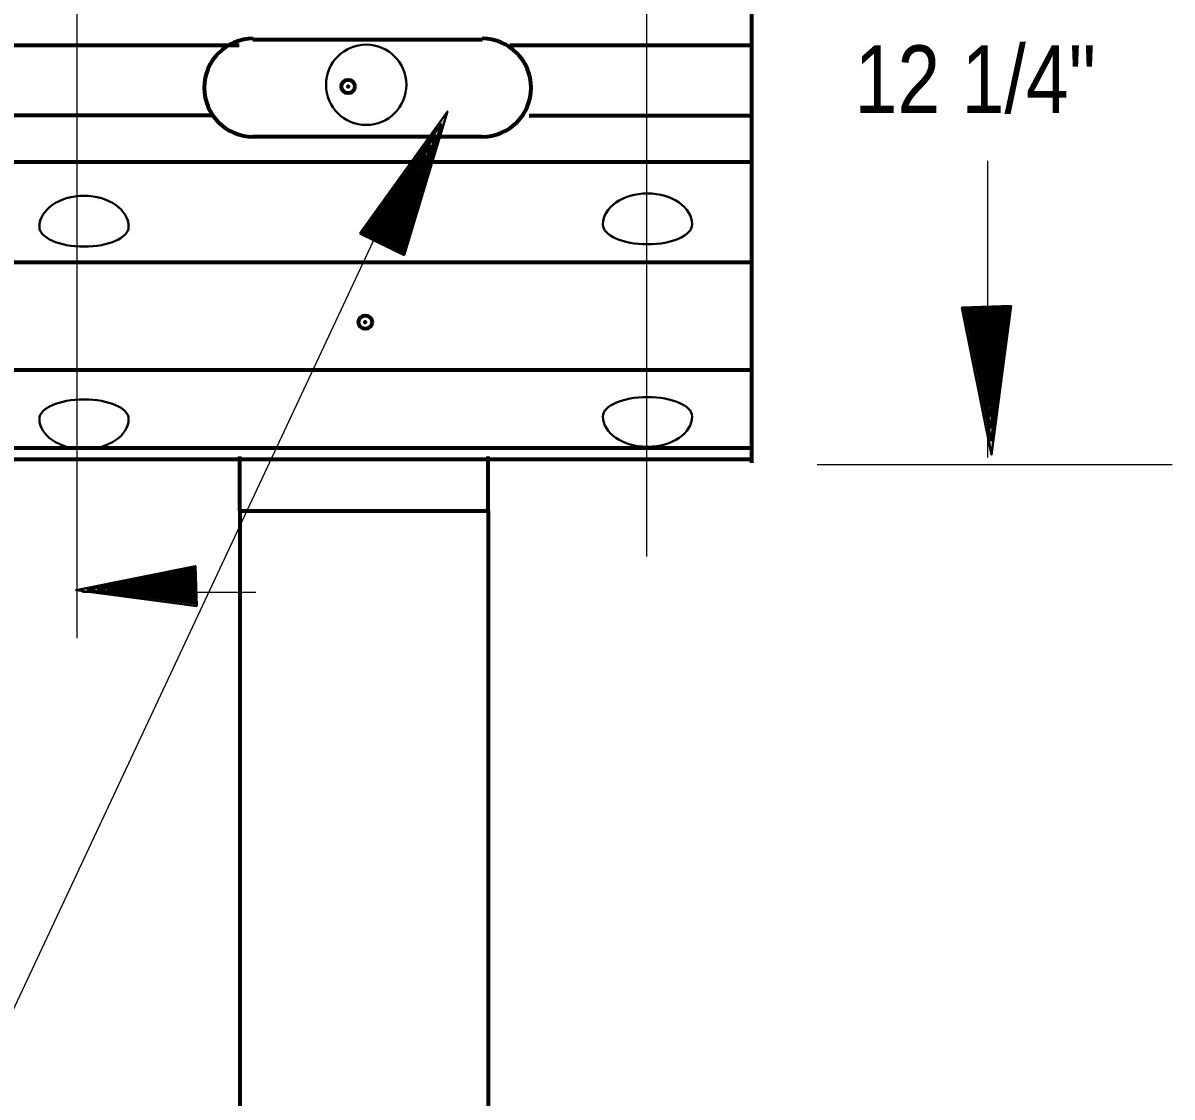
# Model space of a CAD drawing. Extents: x 895.6 to 930.4, y -2278.6 to -2254.7.
# Drawn here: x 921.428 to 923.608, y -2263.475 to -2261.437 of the extents above; entities that cross this region are included whole.
import ezdxf

# ---------------------------------------------------------------- set-up
doc = ezdxf.new("R2010")
doc.units = 0
doc.header["$LTSCALE"] = 0.051
doc.header["$PDMODE"] = 32
doc.header["$PDSIZE"] = 0.0255
for name, color, linetype, lineweight in [('1', 7, 'Continuous', 70), ('3', 7, 'Continuous', 40), ('35', 7, 'Continuous', 70)]:
    doc.layers.add(name, color=color, linetype=linetype, lineweight=lineweight)

msp = doc.modelspace()

# ---------------------------------------------------------------- hatches: boundary and pattern name
at = {"layer": '3'}
for points in [[(922.06675, -2261.83625), (922.15092, -2261.87758), (922.23292, -2261.60483), (922.23292, -2261.60483)], [(922.07158, -2261.83708), (922.14717, -2261.87433), (922.22108, -2261.62892), (922.22108, -2261.62892)], [(922.076, -2261.83792), (922.14392, -2261.87142), (922.21042, -2261.65058), (922.21042, -2261.65058)], [(922.07967, -2261.83875), (922.14075, -2261.86883), (922.20075, -2261.67008), (922.20075, -2261.67008)], [(922.08308, -2261.83942), (922.13817, -2261.86642), (922.19208, -2261.68758), (922.19208, -2261.68758)], [(922.08625, -2261.83983), (922.13592, -2261.86433), (922.18442, -2261.70333), (922.18442, -2261.70333)], [(922.08917, -2261.84067), (922.13375, -2261.86267), (922.17742, -2261.71758), (922.17742, -2261.71758)], [(922.09167, -2261.84083), (922.13167, -2261.86083), (922.171, -2261.73042), (922.171, -2261.73042)], [(922.09367, -2261.84158), (922.13017, -2261.85917), (922.16542, -2261.74192), (922.16542, -2261.74192)], [(922.096, -2261.84183), (922.12875, -2261.85783), (922.16025, -2261.75225), (922.16025, -2261.75225)], [(922.09792, -2261.84217), (922.12708, -2261.85658), (922.15575, -2261.76167), (922.15575, -2261.76167)], [(922.09958, -2261.84267), (922.12575, -2261.85542), (922.15167, -2261.77008), (922.15167, -2261.77008)], [(922.101, -2261.84275), (922.12467, -2261.85442), (922.14775, -2261.77775), (922.14775, -2261.77775)], [(922.10242, -2261.84292), (922.12367, -2261.85367), (922.1445, -2261.78417), (922.1445, -2261.78417)], [(922.10358, -2261.84317), (922.12275, -2261.85275), (922.14142, -2261.79033), (922.14142, -2261.79033)], [(922.10458, -2261.84342), (922.12208, -2261.85217), (922.139, -2261.79592), (922.139, -2261.79592)], [(922.10575, -2261.84375), (922.12142, -2261.85142), (922.1365, -2261.80083), (922.1365, -2261.80083)], [(922.10658, -2261.84392), (922.12058, -2261.85083), (922.13442, -2261.80525), (922.13442, -2261.80525)], [(922.10725, -2261.84375), (922.11992, -2261.85025), (922.13217, -2261.80917), (922.13217, -2261.80917)], [(922.10792, -2261.84392), (922.11925, -2261.84967), (922.1305, -2261.81267), (922.1305, -2261.81267)], [(922.10842, -2261.84375), (922.11875, -2261.84883), (922.12858, -2261.81575), (922.12858, -2261.81575)], [(922.10908, -2261.84417), (922.11825, -2261.84867), (922.12717, -2261.81875), (922.12717, -2261.81875)], [(922.10958, -2261.84425), (922.11792, -2261.84825), (922.12617, -2261.82142), (922.12617, -2261.82142)], [(922.11008, -2261.84425), (922.1175, -2261.84792), (922.12475, -2261.82367), (922.12475, -2261.82367)], [(923.30275, -2261.97392), (923.20917, -2261.97717), (923.26542, -2262.25633), (923.26542, -2262.25633)], [(923.29808, -2261.97542), (923.21383, -2261.97825), (923.26442, -2262.22942), (923.26442, -2262.22942)], [(923.29383, -2261.97667), (923.21817, -2261.97925), (923.26375, -2262.20533), (923.26375, -2262.20533)], [(923.29017, -2261.97783), (923.22208, -2261.98017), (923.26308, -2262.18367), (923.26308, -2262.18367)], [(923.28692, -2261.97875), (923.22558, -2261.98092), (923.26242, -2262.16417), (923.26242, -2262.16417)], [(923.28375, -2261.97992), (923.22858, -2261.98175), (923.26183, -2262.14658), (923.26183, -2262.14658)], [(923.28092, -2261.98067), (923.23125, -2261.98225), (923.26125, -2262.13075), (923.26125, -2262.13075)], [(923.27867, -2261.98158), (923.23383, -2261.98283), (923.26083, -2262.11633), (923.26083, -2262.11633)], [(923.27642, -2261.98192), (923.23608, -2261.98358), (923.26025, -2262.10367), (923.26025, -2262.10367)], [(923.27433, -2261.98275), (923.23792, -2261.98408), (923.25992, -2262.09208), (923.25992, -2262.09208)], [(923.27258, -2261.98333), (923.23992, -2261.98442), (923.25958, -2262.08167), (923.25958, -2262.08167)], [(923.27083, -2261.98375), (923.24167, -2261.98483), (923.25917, -2262.07233), (923.25917, -2262.07233)], [(923.26958, -2261.98433), (923.24308, -2261.98517), (923.25892, -2262.06375), (923.25892, -2262.06375)], [(923.26817, -2261.98483), (923.24433, -2261.98542), (923.25875, -2262.05642), (923.25875, -2262.05642)], [(923.26708, -2261.98517), (923.24558, -2261.98583), (923.25858, -2262.04958), (923.25858, -2262.04958)], [(923.26592, -2261.98542), (923.24658, -2261.98592), (923.25817, -2262.04342), (923.25817, -2262.04342)], [(923.26492, -2261.98575), (923.24742, -2261.98633), (923.25792, -2262.03792), (923.25792, -2262.03792)], [(923.26408, -2261.98592), (923.24842, -2261.98642), (923.25783, -2262.03308), (923.25783, -2262.03308)], [(923.26358, -2261.98633), (923.24933, -2261.98667), (923.25783, -2262.02867), (923.25783, -2262.02867)], [(923.26283, -2261.98658), (923.25017, -2261.98692), (923.25775, -2262.02475), (923.25775, -2262.02475)], [(923.26242, -2261.98683), (923.25092, -2261.98725), (923.25792, -2262.02117), (923.25792, -2262.02117)], [(923.26175, -2261.98683), (923.25158, -2261.98725), (923.25775, -2262.01783), (923.25775, -2262.01783)], [(923.26117, -2261.98708), (923.25208, -2261.98742), (923.25742, -2262.01492), (923.25742, -2262.01492)], [(923.26083, -2261.98725), (923.25267, -2261.98758), (923.25758, -2262.01233), (923.25758, -2262.01233)], [(921.75733, -2262.54333), (921.75483, -2262.46742), (921.52867, -2262.51317), (921.52867, -2262.51317)], [(921.75617, -2262.53942), (921.75392, -2262.47133), (921.55042, -2262.51233), (921.55042, -2262.51233)], [(921.75517, -2262.53617), (921.75317, -2262.47475), (921.56992, -2262.51175), (921.56992, -2262.51175)], [(921.75417, -2262.53308), (921.75233, -2262.47792), (921.58758, -2262.51117), (921.58758, -2262.51117)], [(921.75342, -2262.53058), (921.75167, -2262.48083), (921.60333, -2262.51067), (921.60333, -2262.51067)], [(921.75242, -2262.52792), (921.75108, -2262.48325), (921.61758, -2262.51025), (921.61758, -2262.51025)], [(921.75192, -2262.52575), (921.75067, -2262.48533), (921.63033, -2262.50967), (921.63033, -2262.50967)], [(921.75125, -2262.52383), (921.75017, -2262.48758), (921.64208, -2262.50942), (921.64208, -2262.50942)], [(921.75083, -2262.52208), (921.74967, -2262.48925), (921.65233, -2262.50883), (921.65233, -2262.50883)], [(921.75025, -2262.52033), (921.74917, -2262.49083), (921.66167, -2262.50875), (921.66167, -2262.50875)], [(921.74975, -2262.51883), (921.74883, -2262.49258), (921.67017, -2262.50833), (921.67017, -2262.50833)], [(921.74942, -2262.51758), (921.74858, -2262.49383), (921.67767, -2262.50792), (921.67767, -2262.50792)], [(921.74892, -2262.51642), (921.74833, -2262.49492), (921.68467, -2262.50783), (921.68467, -2262.50783)], [(921.74858, -2262.51525), (921.74808, -2262.49608), (921.69058, -2262.50775), (921.69058, -2262.50775)], [(921.74833, -2262.51433), (921.74775, -2262.49708), (921.69617, -2262.50758), (921.69617, -2262.50758)], [(921.74808, -2262.51358), (921.74767, -2262.49783), (921.70108, -2262.50717), (921.70108, -2262.50717)], [(921.74783, -2262.51275), (921.74733, -2262.49858), (921.70558, -2262.50708), (921.70558, -2262.50708)], [(921.74767, -2262.51192), (921.74725, -2262.49933), (921.70942, -2262.50692), (921.70942, -2262.50692)], [(921.74733, -2262.51158), (921.74708, -2262.50008), (921.71308, -2262.50692), (921.71308, -2262.50692)], [(921.74717, -2262.51108), (921.74683, -2262.50067), (921.71625, -2262.50692), (921.71625, -2262.50692)], [(921.74692, -2262.51067), (921.74667, -2262.50142), (921.71917, -2262.50708), (921.71917, -2262.50708)], [(921.74692, -2262.51017), (921.74667, -2262.50183), (921.72175, -2262.50692), (921.72175, -2262.50692)], [(921.74675, -2262.50967), (921.74642, -2262.50225), (921.72417, -2262.50667), (921.72417, -2262.50667)], [(921.74667, -2262.50942), (921.74633, -2262.50275), (921.72625, -2262.50675), (921.72625, -2262.50675)]]:
    msp.add_hatch(color=256, dxfattribs=at).paths.add_polyline_path(points)

# ---------------------------------------------------------------- linework, layer by layer
at = {"layer": '1', "lineweight": 25}
for p, q in [((921.53067, -2262.60458), (921.53067, -2259.70667)), ((922.61158, -2262.44942), (922.61158, -2259.70667)), ((923.25867, -2262.26183), (923.25867, -2261.69892)), ((922.13808, -2261.75225), (921.36075, -2263.412)), ((923.60783, -2262.27567), (922.93483, -2262.27567)), ((921.86967, -2262.51792), (921.54092, -2262.51792))]:
    msp.add_line(p, q, dxfattribs=at)
at = {"layer": '1'}
for p, q in [((922.81058, -2262.27175), (922.81058, -2260.82867)), ((921.86383, -2261.46833), (922.29883, -2261.46833)), ((921.30733, -2261.47942), (921.83808, -2261.47942)), ((922.35125, -2261.47942), (922.81058, -2261.47942)), ((921.78592, -2261.61267), (921.32442, -2261.61267)), ((922.38842, -2261.61267), (922.81058, -2261.61267)), ((922.29883, -2261.65325), (921.86383, -2261.65325)), ((921.30733, -2261.70042), (921.75167, -2261.70042)), ((921.75167, -2261.70042), (922.81058, -2261.70042)), ((921.30733, -2261.89125), (922.81058, -2261.89125)), ((921.30733, -2262.09508), (922.81058, -2262.09508)), ((922.81058, -2262.24375), (921.30483, -2262.24375)), ((921.30175, -2262.26483), (922.81058, -2262.26483)), ((921.83917, -2262.36283), (921.83917, -2263.93892)), ((922.31042, -2262.36283), (922.31042, -2263.93892))]:
    msp.add_line(p, q, dxfattribs=at)
at = {"layer": '1', "lineweight": 40}
msp.add_circle((922.07902, -2261.5544), 0.07627, dxfattribs=at)
at = {"layer": '1'}
for centre, start, end in [((921.86473, -2261.55994), 90, 270), ((922.29887, -2261.55994), 270, 90)]:
    msp.add_arc(centre, 0.09303, start, end, dxfattribs=at)
at = {"layer": '1', "lineweight": 40}
for centre, major_axis, ratio in [((921.54359, -2261.824), (-0.08469, 0), 0.696674), ((922.61267, -2261.8195), (-0.08469, 0), 0.696674), ((922.61267, -2261.8195), (0.08469, 0), 0.442883), ((921.54359, -2261.824), (0.08469, 0), 0.442883), ((922.61267, -2262.18358), (-0.08469, 0), 0.434256), ((921.54359, -2262.18808), (-0.08469, 0), 0.434256), ((921.54359, -2262.18808), (0.08469, 0), 0.679978), ((922.61267, -2262.18358), (0.08469, 0), 0.679978)]:
    msp.add_ellipse(centre, major_axis=major_axis, ratio=ratio, start_param=3.1415927, end_param=6.2831853, dxfattribs=at)
at = {"layer": '1'}
for p in [(922.04467, -2261.55767), (922.07725, -2262.00475)]:
    msp.add_point(p, dxfattribs=at)
at = {"layer": '3'}
for points in [[(922.06675, -2261.83625), (922.15092, -2261.87758), (922.23292, -2261.60483), (922.23292, -2261.60483)], [(922.07158, -2261.83708), (922.14717, -2261.87433), (922.22108, -2261.62892), (922.22108, -2261.62892)], [(922.076, -2261.83792), (922.14392, -2261.87142), (922.21042, -2261.65058), (922.21042, -2261.65058)], [(922.07967, -2261.83875), (922.14075, -2261.86883), (922.20075, -2261.67008), (922.20075, -2261.67008)], [(922.08308, -2261.83942), (922.13817, -2261.86642), (922.19208, -2261.68758), (922.19208, -2261.68758)], [(922.08625, -2261.83983), (922.13592, -2261.86433), (922.18442, -2261.70333), (922.18442, -2261.70333)], [(922.08917, -2261.84067), (922.13375, -2261.86267), (922.17742, -2261.71758), (922.17742, -2261.71758)], [(922.09167, -2261.84083), (922.13167, -2261.86083), (922.171, -2261.73042), (922.171, -2261.73042)], [(922.09367, -2261.84158), (922.13017, -2261.85917), (922.16542, -2261.74192), (922.16542, -2261.74192)], [(922.096, -2261.84183), (922.12875, -2261.85783), (922.16025, -2261.75225), (922.16025, -2261.75225)], [(922.09792, -2261.84217), (922.12708, -2261.85658), (922.15575, -2261.76167), (922.15575, -2261.76167)], [(922.09958, -2261.84267), (922.12575, -2261.85542), (922.15167, -2261.77008), (922.15167, -2261.77008)], [(922.101, -2261.84275), (922.12467, -2261.85442), (922.14775, -2261.77775), (922.14775, -2261.77775)], [(922.10242, -2261.84292), (922.12367, -2261.85367), (922.1445, -2261.78417), (922.1445, -2261.78417)], [(922.10358, -2261.84317), (922.12275, -2261.85275), (922.14142, -2261.79033), (922.14142, -2261.79033)], [(922.10458, -2261.84342), (922.12208, -2261.85217), (922.139, -2261.79592), (922.139, -2261.79592)], [(922.10575, -2261.84375), (922.12142, -2261.85142), (922.1365, -2261.80083), (922.1365, -2261.80083)], [(922.10658, -2261.84392), (922.12058, -2261.85083), (922.13442, -2261.80525), (922.13442, -2261.80525)], [(922.10725, -2261.84375), (922.11992, -2261.85025), (922.13217, -2261.80917), (922.13217, -2261.80917)], [(922.10792, -2261.84392), (922.11925, -2261.84967), (922.1305, -2261.81267), (922.1305, -2261.81267)], [(922.10842, -2261.84375), (922.11875, -2261.84883), (922.12858, -2261.81575), (922.12858, -2261.81575)], [(922.10908, -2261.84417), (922.11825, -2261.84867), (922.12717, -2261.81875), (922.12717, -2261.81875)], [(922.10958, -2261.84425), (922.11792, -2261.84825), (922.12617, -2261.82142), (922.12617, -2261.82142)], [(922.11008, -2261.84425), (922.1175, -2261.84792), (922.12475, -2261.82367), (922.12475, -2261.82367)], [(923.30275, -2261.97392), (923.20917, -2261.97717), (923.26542, -2262.25633), (923.26542, -2262.25633)], [(923.29808, -2261.97542), (923.21383, -2261.97825), (923.26442, -2262.22942), (923.26442, -2262.22942)], [(923.29383, -2261.97667), (923.21817, -2261.97925), (923.26375, -2262.20533), (923.26375, -2262.20533)], [(923.29017, -2261.97783), (923.22208, -2261.98017), (923.26308, -2262.18367), (923.26308, -2262.18367)], [(923.28692, -2261.97875), (923.22558, -2261.98092), (923.26242, -2262.16417), (923.26242, -2262.16417)], [(923.28375, -2261.97992), (923.22858, -2261.98175), (923.26183, -2262.14658), (923.26183, -2262.14658)], [(923.28092, -2261.98067), (923.23125, -2261.98225), (923.26125, -2262.13075), (923.26125, -2262.13075)], [(923.27867, -2261.98158), (923.23383, -2261.98283), (923.26083, -2262.11633), (923.26083, -2262.11633)], [(923.27642, -2261.98192), (923.23608, -2261.98358), (923.26025, -2262.10367), (923.26025, -2262.10367)], [(923.27433, -2261.98275), (923.23792, -2261.98408), (923.25992, -2262.09208), (923.25992, -2262.09208)], [(923.27258, -2261.98333), (923.23992, -2261.98442), (923.25958, -2262.08167), (923.25958, -2262.08167)], [(923.27083, -2261.98375), (923.24167, -2261.98483), (923.25917, -2262.07233), (923.25917, -2262.07233)], [(923.26958, -2261.98433), (923.24308, -2261.98517), (923.25892, -2262.06375), (923.25892, -2262.06375)], [(923.26817, -2261.98483), (923.24433, -2261.98542), (923.25875, -2262.05642), (923.25875, -2262.05642)], [(923.26708, -2261.98517), (923.24558, -2261.98583), (923.25858, -2262.04958), (923.25858, -2262.04958)], [(923.26592, -2261.98542), (923.24658, -2261.98592), (923.25817, -2262.04342), (923.25817, -2262.04342)], [(923.26492, -2261.98575), (923.24742, -2261.98633), (923.25792, -2262.03792), (923.25792, -2262.03792)], [(923.26408, -2261.98592), (923.24842, -2261.98642), (923.25783, -2262.03308), (923.25783, -2262.03308)], [(923.26358, -2261.98633), (923.24933, -2261.98667), (923.25783, -2262.02867), (923.25783, -2262.02867)], [(923.26283, -2261.98658), (923.25017, -2261.98692), (923.25775, -2262.02475), (923.25775, -2262.02475)], [(923.26242, -2261.98683), (923.25092, -2261.98725), (923.25792, -2262.02117), (923.25792, -2262.02117)], [(923.26175, -2261.98683), (923.25158, -2261.98725), (923.25775, -2262.01783), (923.25775, -2262.01783)], [(923.26117, -2261.98708), (923.25208, -2261.98742), (923.25742, -2262.01492), (923.25742, -2262.01492)], [(923.26083, -2261.98725), (923.25267, -2261.98758), (923.25758, -2262.01233), (923.25758, -2262.01233)], [(921.75733, -2262.54333), (921.75483, -2262.46742), (921.52867, -2262.51317), (921.52867, -2262.51317)], [(921.75617, -2262.53942), (921.75392, -2262.47133), (921.55042, -2262.51233), (921.55042, -2262.51233)], [(921.75517, -2262.53617), (921.75317, -2262.47475), (921.56992, -2262.51175), (921.56992, -2262.51175)], [(921.75417, -2262.53308), (921.75233, -2262.47792), (921.58758, -2262.51117), (921.58758, -2262.51117)], [(921.75342, -2262.53058), (921.75167, -2262.48083), (921.60333, -2262.51067), (921.60333, -2262.51067)], [(921.75242, -2262.52792), (921.75108, -2262.48325), (921.61758, -2262.51025), (921.61758, -2262.51025)], [(921.75192, -2262.52575), (921.75067, -2262.48533), (921.63033, -2262.50967), (921.63033, -2262.50967)], [(921.75125, -2262.52383), (921.75017, -2262.48758), (921.64208, -2262.50942), (921.64208, -2262.50942)], [(921.75083, -2262.52208), (921.74967, -2262.48925), (921.65233, -2262.50883), (921.65233, -2262.50883)], [(921.75025, -2262.52033), (921.74917, -2262.49083), (921.66167, -2262.50875), (921.66167, -2262.50875)], [(921.74975, -2262.51883), (921.74883, -2262.49258), (921.67017, -2262.50833), (921.67017, -2262.50833)], [(921.74942, -2262.51758), (921.74858, -2262.49383), (921.67767, -2262.50792), (921.67767, -2262.50792)], [(921.74892, -2262.51642), (921.74833, -2262.49492), (921.68467, -2262.50783), (921.68467, -2262.50783)], [(921.74858, -2262.51525), (921.74808, -2262.49608), (921.69058, -2262.50775), (921.69058, -2262.50775)], [(921.74833, -2262.51433), (921.74775, -2262.49708), (921.69617, -2262.50758), (921.69617, -2262.50758)], [(921.74808, -2262.51358), (921.74767, -2262.49783), (921.70108, -2262.50717), (921.70108, -2262.50717)], [(921.74783, -2262.51275), (921.74733, -2262.49858), (921.70558, -2262.50708), (921.70558, -2262.50708)], [(921.74767, -2262.51192), (921.74725, -2262.49933), (921.70942, -2262.50692), (921.70942, -2262.50692)], [(921.74733, -2262.51158), (921.74708, -2262.50008), (921.71308, -2262.50692), (921.71308, -2262.50692)], [(921.74717, -2262.51108), (921.74683, -2262.50067), (921.71625, -2262.50692), (921.71625, -2262.50692)], [(921.74692, -2262.51067), (921.74667, -2262.50142), (921.71917, -2262.50708), (921.71917, -2262.50708)], [(921.74692, -2262.51017), (921.74667, -2262.50183), (921.72175, -2262.50692), (921.72175, -2262.50692)], [(921.74675, -2262.50967), (921.74642, -2262.50225), (921.72417, -2262.50667), (921.72417, -2262.50667)], [(921.74667, -2262.50942), (921.74633, -2262.50275), (921.72625, -2262.50675), (921.72625, -2262.50675)]]:
    msp.add_lwpolyline(points, close=True, dxfattribs=at)
at = {"layer": '35'}
for p, q in [((921.83917, -2262.36283), (921.83917, -2262.25967)), ((922.31042, -2262.36283), (922.31042, -2262.25967)), ((921.83917, -2262.36283), (922.31042, -2262.36283))]:
    msp.add_line(p, q, dxfattribs=at)

# ---------------------------------------------------------------- texts
at = {"layer": '1', "width": 0.85}
msp.add_text('12 1/4"', height=0.1286, dxfattribs=at).set_placement((923.00542, -2261.60825))

doc.saveas('drawing.dxf')
